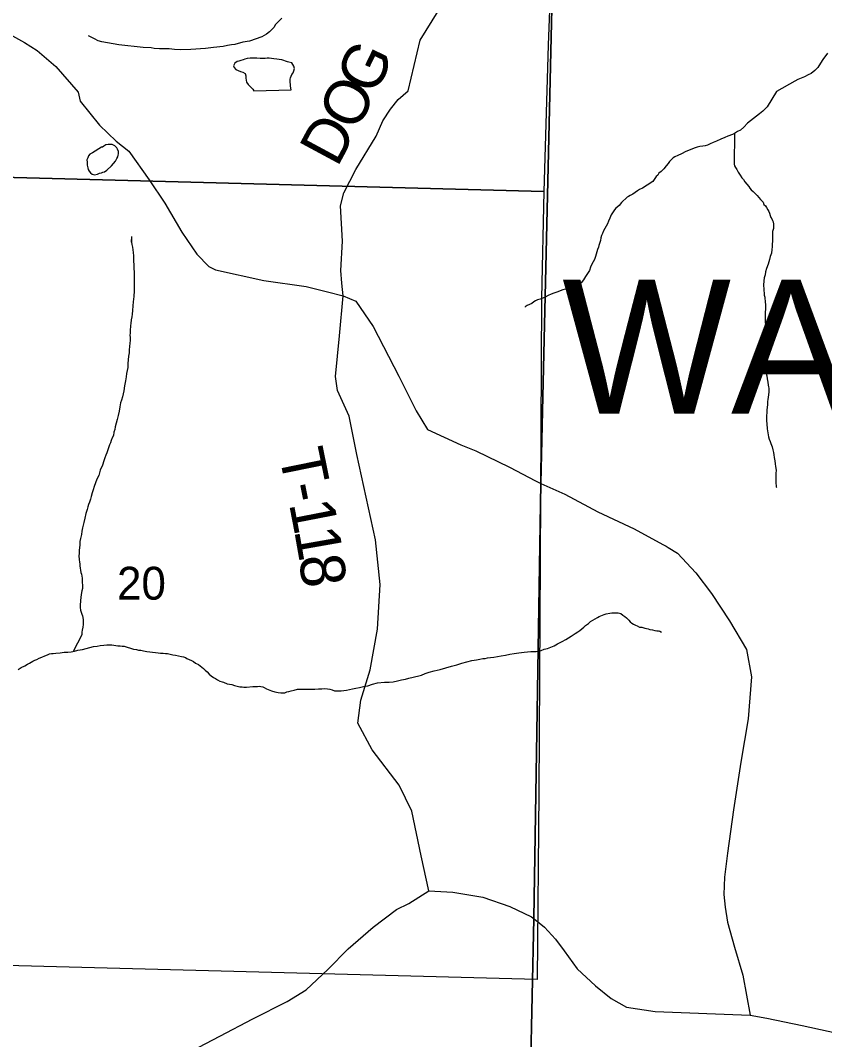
# Model space of a CAD drawing. Extents: x -14196 to 143, y -6096 to 28.
# Drawn here: x 61.569 to 62.594, y 19.711 to 21.01 of the extents above; entities that cross this region are included whole.
import ezdxf

# ---------------------------------------------------------------- set-up
doc = ezdxf.new("R2010")
doc.units = 0
for name, color, linetype in [('GM_X_Corporation', 7, 'Continuous'), ('GM_X_County_Road', 7, 'Continuous'), ('GM_X_Minor_Lake', 7, 'Continuous'), ('GM_X_Minor_River', 7, 'Continuous'), ('GM_X_Section_Text', 7, 'Continuous'), ('GM_X_Township_Road', 7, 'Continuous'), ('GM_X_Township_Road_Text', 7, 'Continuous'), ('GM_X_Township_Text', 7, 'Continuous')]:
    doc.layers.add(name, color=color, linetype=linetype)

msp = doc.modelspace()

# ---------------------------------------------------------------- linework, layer by layer
at = {"layer": 'GM_X_Corporation'}
msp.add_lwpolyline([(62.1999, 18.7816), (62.2235, 19.866), (62.2323, 20.4208), (62.2487, 21.1358), (62.2751, 22.2884), (62.2815, 22.5484), (62.2824, 22.5866), (62.306, 23.4402), (61.9207, 23.4521), (60.7524, 23.485), (60.7179, 23.4857), (60.6994, 23.486), (60.6731, 23.4865), (60.4232, 23.4912), (60.4233, 23.5426), (60.4242, 23.5839), (60.4246, 23.6029), (60.4257, 23.6513), (60.4267, 23.6985), (58.1028, 23.6985), (58.1028, 18.8711)], dxfattribs=at)
for points in [[(64.9028, 18.7286), (64.9028, 23.6985), (62.6174, 23.6985), (62.6129, 23.4358), (62.306, 23.4402), (62.2824, 22.5866), (62.2815, 22.5484), (62.2751, 22.2884), (62.2487, 21.1358), (62.2323, 20.4208), (62.2235, 19.866), (62.1999, 18.7816), (62.384, 18.775), (62.5403, 18.7731), (63.0887, 18.7577), (63.6879, 18.7414), (64.3696, 18.7343), (64.4266, 18.7347)], [(61.9287, 21.423), (62.2585, 21.4234), (62.2418, 20.9787), (62.2362, 20.7922), (61.2237, 20.8189), (61.23, 21.4222), (61.2736, 21.4223), (61.6017, 21.4227)], [(62.2362, 20.7922), (62.2333, 20.6565), (62.2314, 20.3211), (62.2297, 20.027), (62.2277, 19.7879), (61.2122, 19.8148), (61.2237, 20.8189)]]:
    msp.add_lwpolyline(points, close=True, dxfattribs=at)
at = {"layer": 'GM_X_County_Road'}
for points in [[(61.5589, 20.9906), (61.5742, 20.9824), (61.5906, 20.9722), (61.6141, 20.9517), (61.6427, 20.919), (61.6455, 20.9074), (61.6698, 20.8768), (61.6912, 20.8565), (61.7075, 20.8436), (61.7331, 20.807), (61.7532, 20.7774), (61.775, 20.7404), (61.794, 20.7123), (61.8092, 20.6968), (61.8176, 20.6924), (61.8795, 20.6788), (61.9332, 20.6714), (61.9604, 20.6645), (61.9806, 20.6593), (61.9968, 20.6525), (62.0188, 20.6204), (62.0512, 20.557), (62.0736, 20.5127), (62.0879, 20.4891), (62.1302, 20.4693), (62.1493, 20.4618), (62.1924, 20.4412), (62.2255, 20.4234), (62.2325, 20.4202), (62.2628, 20.4065), (62.3051, 20.384), (62.3512, 20.3624), (62.3877, 20.3426)], [(62.3877, 20.3426), (62.3921, 20.3402), (62.3946, 20.3387), (62.4063, 20.3315), (62.4298, 20.3062), (62.4498, 20.2801), (62.4727, 20.245), (62.4945, 20.2087), (62.5007, 20.1739), (62.4964, 20.1202), (62.4871, 20.0652), (62.478, 20.0045), (62.47, 19.9489), (62.4664, 19.9185), (62.4657, 19.8966), (62.4671, 19.8801), (62.4704, 19.8612), (62.4793, 19.8292), (62.4899, 19.7938), (62.4991, 19.7425)], [(61.7697, 19.6877), (61.8233, 19.716), (61.8653, 19.738), (61.9092, 19.76), (61.9335, 19.7751), (61.9609, 19.8009), (61.9869, 19.827), (62.0188, 19.8548), (62.0486, 19.8772), (62.064, 19.8848), (62.0897, 19.9009), (62.1201, 19.8996), (62.1585, 19.893), (62.1929, 19.8811), (62.2206, 19.8679), (62.2237, 19.8654), (62.2372, 19.8546), (62.2511, 19.8394), (62.2619, 19.8246)], [(62.2619, 19.8246), (62.2788, 19.8017), (62.302, 19.7799), (62.3218, 19.764), (62.3417, 19.7527), (62.3781, 19.7475), (62.4991, 19.7425), (62.5203, 19.7389), (62.5653, 19.7296), (62.6883, 19.7028)]]:
    msp.add_lwpolyline(points, dxfattribs=at)
at = {"layer": 'GM_X_Minor_Lake'}
for points in [[(61.9141, 20.922), (61.9138, 20.9239), (61.9134, 20.927), (61.9134, 20.9289), (61.913, 20.9312), (61.913, 20.9334), (61.9129, 20.9353), (61.9133, 20.9372), (61.9152, 20.9414), (61.9167, 20.9437), (61.9175, 20.946), (61.9186, 20.949), (61.9174, 20.9521), (61.9151, 20.9562), (61.9113, 20.957), (61.9094, 20.9577), (61.9071, 20.9585), (61.9049, 20.9592), (61.9022, 20.96), (61.8991, 20.9607), (61.8961, 20.9611), (61.8923, 20.9615), (61.8892, 20.9618), (61.8862, 20.9622), (61.8835, 20.9622), (61.8812, 20.9618), (61.8786, 20.9618), (61.8748, 20.9618), (61.8706, 20.9621), (61.8675, 20.9621), (61.8649, 20.9621), (61.8618, 20.9621), (61.858, 20.9617), (61.855, 20.961), (61.8531, 20.9602), (61.85, 20.9594), (61.8474, 20.9586), (61.8455, 20.9579), (61.8424, 20.956), (61.8406, 20.9525), (61.8417, 20.9503), (61.8436, 20.948), (61.8467, 20.9465), (61.8497, 20.9454), (61.8528, 20.9446), (61.8554, 20.9427), (61.8566, 20.9397), (61.8566, 20.9367), (61.857, 20.934), (61.8574, 20.9317), (61.8593, 20.9287), (61.862, 20.926), (61.8654, 20.9226), (61.8666, 20.9204)], [(61.8666, 20.9204), (61.9141, 20.922)], [(61.6725, 20.8486), (61.6609, 20.8417), (61.6578, 20.8401), (61.656, 20.8378), (61.6549, 20.8352), (61.6537, 20.8325), (61.6542, 20.8298), (61.6542, 20.8276), (61.6542, 20.8257), (61.655, 20.8226), (61.6554, 20.8203), (61.6566, 20.8181), (61.6585, 20.8162), (61.6608, 20.8143), (61.6635, 20.8136), (61.6673, 20.8144), (61.6699, 20.8156), (61.6726, 20.8163), (61.6744, 20.8171), (61.6763, 20.8175), (61.6794, 20.8195), (61.6854, 20.8252), (61.6876, 20.8279), (61.6902, 20.831), (61.6921, 20.8344), (61.6932, 20.8367), (61.6939, 20.8386), (61.6943, 20.8405), (61.6943, 20.8432), (61.6931, 20.8462), (61.6919, 20.8481), (61.6896, 20.8504), (61.6862, 20.8522), (61.6831, 20.8522), (61.6809, 20.8522), (61.6782, 20.8518), (61.6756, 20.8502), (61.6737, 20.849), (61.6725, 20.8486)], [(61.6725, 20.8486), (61.6609, 20.8417), (61.6578, 20.8401), (61.656, 20.8378), (61.6549, 20.8352), (61.6537, 20.8325), (61.6542, 20.8298), (61.6542, 20.8276), (61.6542, 20.8257), (61.655, 20.8226), (61.6554, 20.8203), (61.6566, 20.8181), (61.6585, 20.8162), (61.6608, 20.8143), (61.6635, 20.8136), (61.6673, 20.8144), (61.6699, 20.8156), (61.6726, 20.8163), (61.6744, 20.8171), (61.6763, 20.8175)], [(61.6763, 20.8175), (61.6794, 20.8195), (61.6854, 20.8252), (61.6876, 20.8279), (61.6902, 20.831), (61.6921, 20.8344), (61.6932, 20.8367), (61.6939, 20.8386), (61.6943, 20.8405), (61.6943, 20.8432), (61.6931, 20.8462), (61.6919, 20.8481), (61.6896, 20.8504), (61.6862, 20.8522), (61.6831, 20.8522), (61.6809, 20.8522), (61.6782, 20.8518), (61.6756, 20.8502), (61.6737, 20.849), (61.6725, 20.8486)]]:
    msp.add_lwpolyline(points, dxfattribs=at)
at = {"layer": 'GM_X_Minor_River'}
for points in [[(61.9024, 21.013), (61.8944, 21.0053), (61.8922, 21.0015), (61.8865, 20.9957), (61.8828, 20.993), (61.8767, 20.9896), (61.8612, 20.9841), (61.8524, 20.9825), (61.8426, 20.9797), (61.838, 20.9793), (61.8331, 20.9785), (61.8274, 20.9773), (61.8152, 20.976), (61.8049, 20.9744), (61.7863, 20.9731), (61.7733, 20.973), (61.7654, 20.9733), (61.7589, 20.974), (61.7463, 20.9742), (61.7398, 20.9746), (61.736, 20.9753), (61.7254, 20.9759), (61.6945, 20.9791), (61.6728, 20.983), (61.6682, 20.9845), (61.6636, 20.9868), (61.6559, 20.9909)], [(62.5975, 20.9688), (62.5915, 20.9604), (62.5889, 20.9558), (62.5855, 20.9504), (62.5817, 20.9466), (62.5768, 20.9427), (62.573, 20.9412), (62.5685, 20.9385), (62.5598, 20.935), (62.556, 20.933), (62.5327, 20.9197)], [(62.5327, 20.9197), (62.5209, 20.9002), (62.5182, 20.8975), (62.5152, 20.8948), (62.5111, 20.8914), (62.4957, 20.8794), (62.4912, 20.8741), (62.4866, 20.8706), (62.4829, 20.8687), (62.4802, 20.8671), (62.4765, 20.8648), (62.4708, 20.8628), (62.4666, 20.8613), (62.4617, 20.8589), (62.4561, 20.8566), (62.4519, 20.8546), (62.4481, 20.8531), (62.4447, 20.8515), (62.4417, 20.8507), (62.4387, 20.8499), (62.4349, 20.8495), (62.4315, 20.8487), (62.4277, 20.8475), (62.4228, 20.8456), (62.4171, 20.8433), (62.4114, 20.8405), (62.4069, 20.8382), (62.4031, 20.8363), (62.4009, 20.8351), (62.3978, 20.8324), (62.3963, 20.8305), (62.3945, 20.8282), (62.3919, 20.8251), (62.3889, 20.8213), (62.3855, 20.8178), (62.3829, 20.8155), (62.3814, 20.8132), (62.3791, 20.8113), (62.375, 20.8052), (62.3678, 20.8002), (62.3618, 20.7967), (62.358, 20.7947), (62.3554, 20.7932), (62.3524, 20.7909), (62.3494, 20.7889), (62.346, 20.7874), (62.3441, 20.7859), (62.3422, 20.7851), (62.3351, 20.7782), (62.3321, 20.7743), (62.3298, 20.7724), (62.3279, 20.7709), (62.3264, 20.7689), (62.3246, 20.7663), (62.322, 20.7624), (62.3201, 20.7582), (62.3186, 20.7544), (62.3171, 20.751), (62.3157, 20.7483), (62.3138, 20.7452), (62.3123, 20.7422), (62.3108, 20.7388), (62.3097, 20.7361), (62.309, 20.7334), (62.3083, 20.73), (62.3072, 20.7262), (62.3061, 20.7235), (62.3057, 20.7212), (62.3046, 20.7182), (62.3035, 20.7155), (62.3028, 20.7124), (62.3021, 20.7094), (62.3006, 20.7056), (62.2991, 20.7025), (62.2973, 20.6995), (62.2958, 20.696), (62.2943, 20.6918), (62.2917, 20.688), (62.2891, 20.6838), (62.2869, 20.6796), (62.2839, 20.6761), (62.282, 20.6746), (62.2797, 20.6727), (62.2774, 20.6719), (62.2744, 20.6707), (62.271, 20.6699), (62.2676, 20.6687), (62.2638, 20.6679), (62.2604, 20.6671), (62.2529, 20.664), (62.2491, 20.6628), (62.2453, 20.6613), (62.2415, 20.6597), (62.2377, 20.6578), (62.2347, 20.6562), (62.2313, 20.6551), (62.2283, 20.6543), (62.2256, 20.6531), (62.2234, 20.6516), (62.2207, 20.6496)], [(62.4791, 20.8664), (62.4788, 20.8272), (62.4792, 20.8249), (62.4804, 20.823), (62.4819, 20.8204), (62.4839, 20.817), (62.4862, 20.8132), (62.4885, 20.8098), (62.4904, 20.8076), (62.4924, 20.8045), (62.4947, 20.8015), (62.4974, 20.7985), (62.4985, 20.7966), (62.5005, 20.7944), (62.5028, 20.7925), (62.5078, 20.7872), (62.5101, 20.7846), (62.5124, 20.7823), (62.5155, 20.7786), (62.5166, 20.7759), (62.5186, 20.774), (62.5197, 20.7718), (62.5217, 20.7691), (62.5228, 20.7669), (62.5236, 20.7646), (62.5244, 20.7619), (62.5256, 20.7593), (62.5267, 20.7574), (62.5275, 20.7555), (62.5283, 20.7536), (62.5287, 20.7506), (62.5288, 20.7453), (62.5277, 20.7414), (62.5277, 20.7373), (62.5274, 20.7327), (62.5275, 20.7289), (62.5271, 20.7251), (62.5272, 20.7217), (62.5268, 20.7182), (62.5261, 20.7137), (62.5247, 20.7095), (62.5236, 20.7057), (62.5221, 20.6996), (62.5199, 20.6942), (62.5188, 20.69), (62.5181, 20.6862), (62.517, 20.6824), (62.5163, 20.6786), (62.5163, 20.6767), (62.516, 20.6748), (62.516, 20.6721), (62.5164, 20.6687), (62.5164, 20.6661), (62.5169, 20.6627), (62.5169, 20.66), (62.5177, 20.6577), (62.5177, 20.6554), (62.5181, 20.6528), (62.5181, 20.6509), (62.5185, 20.6486), (62.5186, 20.6456), (62.5186, 20.6425), (62.5183, 20.6387), (62.5184, 20.6292), (62.5184, 20.6273), (62.5184, 20.625), (62.5185, 20.6231), (62.5185, 20.6209), (62.5181, 20.6182), (62.5178, 20.6159), (62.5182, 20.6136), (62.5182, 20.6106), (62.5187, 20.6076), (62.5187, 20.6049), (62.5191, 20.6011), (62.5188, 20.5984), (62.5192, 20.5962), (62.5192, 20.5935), (62.5189, 20.5901), (62.5189, 20.5867), (62.5186, 20.584), (62.5186, 20.5821), (62.5186, 20.5802), (62.5186, 20.5783), (62.5187, 20.5749), (62.5187, 20.5703), (62.5188, 20.5665), (62.5192, 20.5635), (62.5196, 20.5605), (62.5204, 20.5574), (62.5208, 20.5536), (62.5216, 20.5495), (62.522, 20.5457), (62.5225, 20.5434), (62.5229, 20.5415), (62.5229, 20.5392), (62.5229, 20.5369)], [(61.7107, 20.735), (61.7108, 20.7278), (61.7108, 20.7312), (61.7108, 20.7278), (61.7112, 20.7248), (61.712, 20.7214), (61.7125, 20.718), (61.7129, 20.7145), (61.7133, 20.7104), (61.7134, 20.7058), (61.714, 20.6872), (61.7141, 20.6804), (61.7141, 20.6731), (61.7142, 20.6659), (61.7136, 20.6583), (61.7129, 20.6518), (61.7126, 20.6465), (61.7122, 20.6408), (61.7115, 20.6362), (61.7112, 20.6328), (61.7105, 20.6286), (61.7098, 20.6241), (61.7094, 20.6214), (61.7095, 20.6195), (61.7091, 20.6168), (61.7091, 20.6149), (61.7092, 20.6119), (61.7088, 20.6092), (61.7089, 20.6062), (61.7089, 20.6028), (61.7086, 20.5986), (61.7082, 20.5952), (61.7079, 20.5902), (61.7076, 20.5868), (61.7069, 20.5826), (61.7065, 20.578), (61.7062, 20.5731), (61.7059, 20.5682), (61.7052, 20.564), (61.7045, 20.5602), (61.7038, 20.556), (61.7031, 20.551), (61.702, 20.5445), (61.7009, 20.5381), (61.6991, 20.5308), (61.698, 20.5263), (61.6969, 20.5228), (61.6959, 20.5179), (61.6948, 20.5122), (61.6937, 20.5068), (61.6926, 20.5019), (61.6912, 20.4969), (61.6901, 20.4924), (61.6894, 20.4889), (61.6883, 20.4855), (61.6876, 20.4813), (61.6861, 20.4786), (61.685, 20.4752), (61.6839, 20.4721), (61.6828, 20.4695), (61.6791, 20.4592), (61.678, 20.4565), (61.6769, 20.4531), (61.6754, 20.4489), (61.6736, 20.4435), (61.671, 20.4374), (61.6692, 20.4306), (61.6666, 20.4256), (61.6647, 20.421), (61.6633, 20.4164), (61.6618, 20.4123), (61.6607, 20.4081), (61.6592, 20.4035), (61.6585, 20.4001), (61.657, 20.3966), (61.6559, 20.3936), (61.6552, 20.3905), (61.6541, 20.3871), (61.6527, 20.3818), (61.6512, 20.376), (61.6498, 20.3703), (61.649, 20.3669), (61.6483, 20.3635), (61.6476, 20.3593), (61.6469, 20.3551), (61.6458, 20.3501), (61.6451, 20.3463), (61.6448, 20.3414), (61.6441, 20.3353), (61.6442, 20.3311), (61.6438, 20.3281), (61.6442, 20.3235), (61.6443, 20.3201), (61.6447, 20.3178), (61.6451, 20.3152), (61.6455, 20.3125), (61.6459, 20.3099), (61.6463, 20.3068), (61.6471, 20.3045), (61.6475, 20.3019), (61.648, 20.2996)], [(62.2207, 20.6496), (62.2181, 20.6485), (62.2151, 20.6469), (62.2124, 20.6454), (62.2124, 20.645)], [(62.5229, 20.5369), (62.5226, 20.5331), (62.5219, 20.5301), (62.5215, 20.5274), (62.5212, 20.5247), (62.5212, 20.5209), (62.5209, 20.5171), (62.5205, 20.5141), (62.5202, 20.5103), (62.5199, 20.5069), (62.5199, 20.5042), (62.5199, 20.5019), (62.5199, 20.4996), (62.5204, 20.4966), (62.5204, 20.4943), (62.5208, 20.4921), (62.5208, 20.4898), (62.522, 20.4822), (62.5225, 20.4795), (62.5233, 20.4765), (62.5244, 20.4739), (62.5256, 20.4712), (62.5272, 20.467), (62.528, 20.4633), (62.5288, 20.4598), (62.5292, 20.4568), (62.5296, 20.4534), (62.5304, 20.4492), (62.5308, 20.4454), (62.5313, 20.442), (62.5317, 20.4397), (62.5321, 20.4367), (62.5317, 20.4333), (62.5318, 20.4283), (62.5318, 20.4257), (62.5319, 20.4238), (62.5319, 20.4219), (62.5319, 20.42), (62.5323, 20.4177), (62.5323, 20.4158), (62.5325, 20.4152)], [(61.648, 20.2996), (61.648, 20.297), (61.648, 20.2935), (61.6484, 20.2909), (61.6481, 20.2886), (61.6481, 20.2863), (61.6474, 20.2836), (61.647, 20.2814), (61.6467, 20.2783), (61.646, 20.2753), (61.6453, 20.2654), (61.6454, 20.262), (61.6458, 20.2589), (61.6466, 20.2563), (61.6474, 20.2536), (61.6481, 20.2517), (61.649, 20.2468), (61.649, 20.2434), (61.649, 20.2407), (61.6487, 20.2369), (61.648, 20.2335), (61.6476, 20.2308), (61.6473, 20.2274), (61.6364, 20.2061)], [(61.9182, 20.1569), (61.9224, 20.1581), (61.9292, 20.1582), (61.9341, 20.1582), (61.9391, 20.1579), (61.9444, 20.158), (61.9489, 20.1584), (61.9531, 20.1584), (61.9569, 20.1588), (61.9607, 20.1585), (61.9634, 20.1582), (61.9664, 20.1571), (61.9695, 20.1559), (61.9744, 20.156), (61.9778, 20.156), (61.9812, 20.1564), (61.9847, 20.1569), (61.9885, 20.1577), (61.9922, 20.1585), (61.9968, 20.1593), (62.0013, 20.1601), (62.0063, 20.1613), (62.0119, 20.1625), (62.018, 20.1644), (62.0244, 20.166), (62.0332, 20.1669), (62.0389, 20.1669), (62.0442, 20.1674), (62.0495, 20.1686), (62.0548, 20.1698), (62.0597, 20.171), (62.0642, 20.1721), (62.0767, 20.1753), (62.0801, 20.1761), (62.0851, 20.1781), (62.09, 20.1796), (62.0964, 20.1816), (62.104, 20.1832), (62.1112, 20.1852), (62.1184, 20.1872), (62.1252, 20.1891), (62.1316, 20.1911), (62.1381, 20.1931), (62.1445, 20.1947), (62.1502, 20.1955), (62.1544, 20.1963), (62.1585, 20.1971), (62.1612, 20.1971), (62.1642, 20.1979), (62.168, 20.1983), (62.1726, 20.1988), (62.1771, 20.1996), (62.182, 20.2004), (62.1873, 20.2016), (62.193, 20.2028), (62.1983, 20.2036), (62.2044, 20.2044), (62.2112, 20.2053), (62.2154, 20.2057), (62.2196, 20.2061), (62.223, 20.2061), (62.2264, 20.2062), (62.2294, 20.2066), (62.2329, 20.2074), (62.2366, 20.2089), (62.2408, 20.2101), (62.245, 20.2117), (62.2495, 20.2133), (62.2536, 20.216), (62.2597, 20.2187), (62.2642, 20.2214), (62.2676, 20.2237), (62.271, 20.2257), (62.2736, 20.2272), (62.2763, 20.2291), (62.2793, 20.2311), (62.2819, 20.233), (62.2846, 20.2349), (62.2872, 20.2372), (62.2894, 20.2391), (62.2932, 20.2418), (62.2955, 20.2442), (62.3045, 20.2496), (62.3068, 20.2507), (62.309, 20.2515), (62.3109, 20.2523), (62.3132, 20.2531), (62.3155, 20.2539), (62.3204, 20.2551), (62.3227, 20.2555), (62.3246, 20.2555), (62.3272, 20.2555), (62.3307, 20.2552), (62.3341, 20.2544), (62.3368, 20.2526), (62.3394, 20.2507), (62.3417, 20.2492), (62.3444, 20.2462), (62.346, 20.2439), (62.3483, 20.2424), (62.3506, 20.2409)], [(62.3506, 20.2409), (62.3529, 20.2398), (62.3552, 20.2387), (62.3582, 20.2372), (62.3609, 20.2369), (62.3647, 20.2358), (62.367, 20.2354), (62.3693, 20.2351), (62.3712, 20.2343), (62.3746, 20.2336), (62.3776, 20.2329), (62.3803, 20.2325), (62.3822, 20.2325), (62.3841, 20.2322), (62.3845, 20.2326), (62.3841, 20.2322), (62.386, 20.2307)], [(61.5809, 20.1914), (61.5828, 20.1925), (61.585, 20.1937), (61.5877, 20.1949), (61.5903, 20.196), (61.593, 20.1976), (61.5964, 20.1987), (61.6005, 20.2007), (61.6035, 20.2019), (61.6062, 20.203), (61.6088, 20.2034), (61.6111, 20.2035), (61.6145, 20.2039), (61.6198, 20.2043), (61.6248, 20.2051), (61.6297, 20.2052), (61.6339, 20.2056), (61.638, 20.2064), (61.6422, 20.208), (61.6483, 20.2088), (61.6528, 20.21), (61.6577, 20.2112), (61.6623, 20.2124), (61.6668, 20.2128), (61.671, 20.2136), (61.6756, 20.214), (61.6794, 20.2144), (61.6832, 20.2145), (61.6858, 20.2145), (61.6881, 20.2141), (61.6908, 20.2138), (61.6934, 20.2134), (61.6961, 20.2135), (61.6987, 20.2131), (61.7014, 20.2128), (61.7132, 20.2091), (61.717, 20.2088), (61.7197, 20.208), (61.7227, 20.2077), (61.7262, 20.207), (61.7303, 20.2062), (61.7342, 20.2055), (61.7376, 20.2052), (61.7414, 20.2048), (61.7448, 20.2045), (61.7478, 20.2041), (61.7509, 20.2038), (61.7539, 20.2034), (61.7566, 20.2035), (61.76, 20.2028), (61.7634, 20.202), (61.7669, 20.2013), (61.7707, 20.2006), (61.7745, 20.1999), (61.7772, 20.1991), (61.7794, 20.1984), (61.7814, 20.1973), (61.7844, 20.1958), (61.7871, 20.1947), (61.7898, 20.1932), (61.7924, 20.1913), (61.7959, 20.1894), (61.7982, 20.188), (61.8024, 20.1846), (61.8047, 20.1823), (61.807, 20.1801), (61.8097, 20.1774), (61.8124, 20.1752), (61.8151, 20.1729), (61.8177, 20.1718), (61.8204, 20.1699), (61.8235, 20.1681), (61.8261, 20.1673), (61.8281, 20.167), (61.8326, 20.1651), (61.8357, 20.1644), (61.8387, 20.1641), (61.8418, 20.1629), (61.8452, 20.1618), (61.8486, 20.1611), (61.8517, 20.1612), (61.854, 20.1608), (61.8574, 20.1605), (61.8653, 20.1613), (61.8684, 20.1617), (61.8714, 20.1617), (61.8737, 20.1618), (61.8756, 20.1614), (61.8779, 20.1611), (61.8798, 20.1603), (61.8828, 20.1584), (61.889, 20.1558), (61.8935, 20.1548), (61.8977, 20.154), (61.9011, 20.1533), (61.9042, 20.1534), (61.9061, 20.1534), (61.9087, 20.1545), (61.9114, 20.1553), (61.9144, 20.1561), (61.9182, 20.1569)], [(61.5665, 20.1832), (61.5703, 20.1855), (61.5748, 20.1879), (61.5782, 20.1898), (61.5809, 20.1914)]]:
    msp.add_lwpolyline(points, dxfattribs=at)
at = {"layer": 'GM_X_Township_Road'}
msp.add_lwpolyline([(62.0897, 19.9009), (62.0797, 19.9459), (62.0678, 20.0028), (62.0519, 20.0359), (62.0175, 20.0809), (61.999, 20.1147), (62.0031, 20.1441), (62.0147, 20.1827), (62.0244, 20.2347), (62.0275, 20.2914), (62.0215, 20.3483), (61.9979, 20.4571), (61.9879, 20.5059), (61.9731, 20.5386), (61.9707, 20.5564), (61.9759, 20.6083), (61.9806, 20.6593), (61.9787, 20.6756), (61.9775, 20.6916), (61.9796, 20.7292), (61.977, 20.774), (61.9811, 20.7905), (61.9967, 20.8205), (62.0226, 20.863), (62.0308, 20.8822), (62.0407, 20.8973), (62.0507, 20.9097), (62.0632, 20.9206), (62.0786, 20.985), (62.1013, 21.0222)], dxfattribs=at)

# ---------------------------------------------------------------- texts
at = {"layer": 'GM_X_Section_Text'}
msp.add_text('20', height=0.04186, rotation=0, dxfattribs=at).set_placement((61.6923, 20.2722))
at = {"layer": 'GM_X_Township_Road_Text'}
for s, rotation, p in [('G', 64.3263, (62.0205, 20.913)), ('O', 62.9132, (61.997, 20.8671)), ('D', 61.698, (61.9727, 20.8219)), ('T', 281.5117, (61.8982, 20.4591)), ('-', 281.4018, (61.9067, 20.4175)), ('1', 280.9956, (61.9113, 20.3947)), ('1', 279.9953, (61.9179, 20.3606)), ('8', 277.1483, (61.9239, 20.3269))]:
    msp.add_text(s, height=0.0568, rotation=rotation, dxfattribs=at).set_placement(p)
at = {"layer": 'GM_X_Township_Text'}
msp.add_text('WASHINGTON', height=0.17045, rotation=0, dxfattribs=at).set_placement((62.2596, 20.5094))

doc.saveas('drawing.dxf')
